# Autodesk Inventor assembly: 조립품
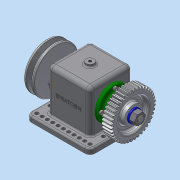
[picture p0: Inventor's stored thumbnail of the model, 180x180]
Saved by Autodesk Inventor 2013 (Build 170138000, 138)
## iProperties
Created: 2018-11
Part Number: 조립품
Document SubType Name: Assembly
Designer: dgall
Author: dgall
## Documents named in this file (13)
- C:\Users\dgall\Desktop\481107V1010\조립품.iam
- C:\Users\dgall\Desktop\481107V1010\본체.ipt
- C:\Users\dgall\Desktop\481107V1010\축.ipt
- C:\Users\dgall\Desktop\481107V1010\베어링 6203.ipt
- C:\Users\dgall\Desktop\481107V1010\키 5x5x12.ipt
- C:\Users\dgall\Desktop\481107V1010\부시.ipt
- C:\Users\dgall\Desktop\481107V1010\V벨트풀리.ipt
- C:\Users\dgall\Desktop\481107V1010\스퍼기어.ipt
- C:\Users\dgall\Desktop\481107V1010\너트 M12x1.25.ipt
- C:\Users\dgall\Desktop\481107V1010\와셔 12x24.ipt
- C:\Users\dgall\Desktop\481107V1010\커버.ipt
- C:\Users\dgall\Desktop\481107V1010\오일 실 26 38 8.ipt
- C:\Users\dgall\Desktop\481107V1010\볼트 M4.ipt
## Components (1 placed, 1 different names)
1. V벨트풀리:1
